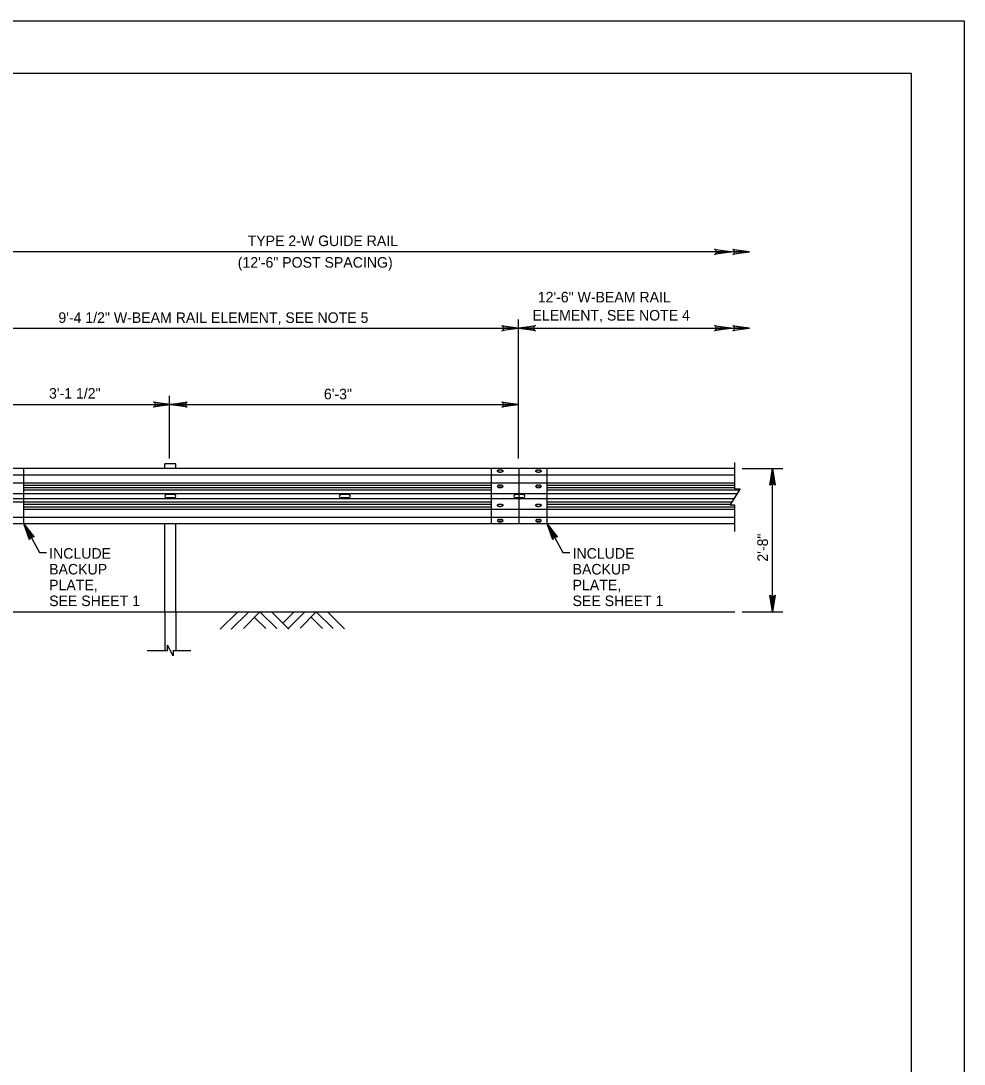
# Model space of a CAD drawing. Extents: x 637628 to 640188, y 298266 to 300751.
# Drawn here: x 639692 to 639960.5, y 299156.6 to 299453.6 of the extents above; entities that cross this region are included whole.
import ezdxf

# ---------------------------------------------------------------- set-up
doc = ezdxf.new("R2010")
doc.units = 0
for name, color, linetype in [('1', 7, 'Continuous'), ('2', 7, 'Continuous'), ('PLT-BNDY', 7, 'Continuous'), ('S-ABUT-CONC', 7, 'Continuous'), ('S-ANNO-CELL', 7, 'Continuous')]:
    doc.layers.add(name, color=color, linetype=linetype)

msp = doc.modelspace()

# ---------------------------------------------------------------- linework, layer by layer
at = {"layer": '1'}
for p, q in [((639692.9, 299310.39), (639692.9, 299326.12)), ((639825.97, 299310.39), (639825.97, 299326.12)), ((639841.88, 299310.39), (639841.88, 299326.12))]:
    msp.add_line(p, q, dxfattribs=at)
msp.add_lwpolyline([(639945.52, 298874.58), (639945.52, 299438.55), (639159.55, 299438.55), (639159.55, 298874.58), (639945.52, 298874.58), (639945.52, 298900.93), (639745.53, 298900.93), (639745.53, 298965.61), (639945.52, 298965.61), (639945.52, 298994.57), (639745.53, 298994.57), (639745.53, 298874.58), (639824.33, 298874.58), (639824.33, 298900.93), (639824.33, 298874.58), (639901.33, 298874.58), (639901.33, 298900.93), (639901.33, 298888.62), (639945.52, 298888.62)], dxfattribs=at)
at = {"layer": '2'}
for p, q in [((639753.59, 299285.19), (639748.82, 299280.42)), ((639756.7, 299285.19), (639751.92, 299280.42)), ((639760.11, 299285.32), (639755.38, 299280.59)), ((639764.88, 299280.55), (639760.11, 299285.32)), ((639768.29, 299280.42), (639763.56, 299285.15)), ((639769.71, 299285.29), (639766.57, 299282.14)), ((639772.82, 299285.29), (639768.05, 299280.52)), ((639776.13, 299285.32), (639771.5, 299280.69)), ((639780.91, 299280.55), (639776.13, 299285.32)), ((639784.15, 299280.52), (639779.35, 299285.32)), ((639761.77, 299280.55), (639758.55, 299283.77)), ((639777.9, 299280.56), (639774.68, 299283.78))]:
    msp.add_line(p, q, dxfattribs=at)
for points in [[(639889.73, 299388.36), (639889.89, 299388.03), (639894.26, 299387.79), (639889.73, 299388.36), (639889.49, 299388.56), (639894.26, 299387.79), (639889.9, 299387.58), (639889.74, 299387.25), (639894.26, 299387.79), (639889.49, 299387.03), (639889.74, 299387.25)], [(639894.92, 299388.38), (639895.09, 299388.06), (639899.46, 299387.82), (639894.92, 299388.38), (639894.69, 299388.58), (639899.46, 299387.82), (639895.09, 299387.6), (639894.93, 299387.27), (639899.46, 299387.82), (639894.69, 299387.06), (639894.93, 299387.27)], [(639829.17, 299366.65), (639829.34, 299366.32), (639833.71, 299366.09), (639829.17, 299366.65), (639828.94, 299366.85), (639833.71, 299366.09), (639829.35, 299365.87), (639829.18, 299365.54), (639833.71, 299366.09), (639828.94, 299365.32), (639829.18, 299365.54)], [(639838.25, 299365.52), (639838.08, 299365.85), (639833.71, 299366.09), (639838.25, 299365.52), (639838.48, 299365.32), (639833.71, 299366.09), (639838.08, 299366.3), (639838.24, 299366.63), (639833.71, 299366.09), (639838.48, 299366.85), (639838.24, 299366.63)], [(639889.73, 299366.63), (639889.89, 299366.3), (639894.26, 299366.06), (639889.73, 299366.63), (639889.49, 299366.83), (639894.26, 299366.06), (639889.9, 299365.85), (639889.74, 299365.52), (639894.26, 299366.06), (639889.49, 299365.3), (639889.74, 299365.52)], [(639894.92, 299366.65), (639895.09, 299366.32), (639899.46, 299366.09), (639894.92, 299366.65), (639894.69, 299366.85), (639899.46, 299366.09), (639895.09, 299365.87), (639894.93, 299365.54), (639899.46, 299366.09), (639894.69, 299365.32), (639894.93, 299365.54)], [(639730.06, 299344.9), (639730.23, 299344.57), (639734.6, 299344.33), (639730.06, 299344.9), (639729.83, 299345.1), (639734.6, 299344.33), (639730.24, 299344.12), (639730.08, 299343.79), (639734.6, 299344.33), (639729.83, 299343.57), (639730.08, 299343.79)], [(639739.14, 299343.76), (639738.97, 299344.09), (639734.6, 299344.33), (639739.14, 299343.76), (639739.38, 299343.56), (639734.6, 299344.33), (639738.97, 299344.55), (639739.13, 299344.87), (639734.6, 299344.33), (639739.38, 299345.09), (639739.13, 299344.87)], [(639829.17, 299344.9), (639829.34, 299344.57), (639833.71, 299344.33), (639829.17, 299344.9), (639828.94, 299345.1), (639833.71, 299344.33), (639829.35, 299344.12), (639829.18, 299343.79), (639833.71, 299344.33), (639828.94, 299343.57), (639829.18, 299343.79)], [(639905.41, 299321.63), (639905.74, 299321.79), (639905.98, 299326.17), (639905.41, 299321.63), (639905.21, 299321.39), (639905.98, 299326.17), (639906.19, 299321.8), (639906.52, 299321.64), (639905.98, 299326.17), (639906.74, 299321.39), (639906.52, 299321.64)], [(639694.57, 299306.13), (639694.77, 299306.43), (639692.9, 299310.39), (639694.57, 299306.13), (639694.5, 299305.83), (639692.9, 299310.39), (639695.17, 299306.65), (639695.54, 299306.67), (639692.9, 299310.39), (639695.84, 299306.56), (639695.54, 299306.67)], [(639843.55, 299306.13), (639843.75, 299306.43), (639841.88, 299310.39), (639843.55, 299306.13), (639843.48, 299305.83), (639841.88, 299310.39), (639844.15, 299306.65), (639844.52, 299306.67), (639841.88, 299310.39), (639844.82, 299306.56), (639844.52, 299306.67)], [(639906.54, 299289.87), (639906.21, 299289.7), (639905.98, 299285.33), (639906.54, 299289.87), (639906.74, 299290.1), (639905.98, 299285.33), (639905.76, 299289.69), (639905.43, 299289.85), (639905.98, 299285.33), (639905.21, 299290.1), (639905.43, 299289.85)]]:
    msp.add_lwpolyline(points, dxfattribs=at)
at = {"layer": 'PLT-BNDY'}
msp.add_lwpolyline([(639119.52, 299453.58), (639960.52, 299453.58), (639960.52, 298859.58), (639119.52, 298859.58)], close=True, dxfattribs=at)
at = {"layer": 'S-ABUT-CONC'}
for p, q in [((639899.46, 299387.84), (639684.94, 299387.84)), ((639833.71, 299328.97), (639833.71, 299368.55)), ((639684.94, 299366.09), (639833.71, 299366.09)), ((639833.71, 299366.09), (639899.46, 299366.09)), ((639734.39, 299328.97), (639734.39, 299346.82)), ((639684.94, 299344.33), (639734.6, 299344.33)), ((639734.6, 299344.33), (639833.71, 299344.33)), ((639897.33, 299326.17), (639908.91, 299326.17)), ((639905.98, 299285.33), (639905.98, 299326.17)), ((639692.9, 299310.39), (639697.31, 299302.27)), ((639841.88, 299310.39), (639846.29, 299302.27)), ((639697.31, 299302.27), (639699.3, 299302.27)), ((639846.29, 299302.27), (639848.28, 299302.27)), ((639897.33, 299285.33), (639908.91, 299285.33))]:
    msp.add_line(p, q, dxfattribs=at)
at = {"layer": 'S-ANNO-CELL'}
for p, q in [((639895.3, 299326.12), (639676.99, 299326.12)), ((639736.19, 299327.51), (639733.01, 299327.51)), ((639733.01, 299326.12), (639733.01, 299327.51)), ((639736.19, 299326.12), (639736.19, 299327.51)), ((639828.31, 299325.77), (639828.63, 299325.77)), ((639828.31, 299325.66), (639828.31, 299325.77)), ((639828.63, 299325.66), (639828.31, 299325.66)), ((639828.63, 299325.66), (639828.63, 299325.77)), ((639833.92, 299310.52), (639833.92, 299326.12)), ((639839.22, 299325.77), (639839.54, 299325.77)), ((639839.22, 299325.66), (639839.22, 299325.77)), ((639839.54, 299325.66), (639839.22, 299325.66)), ((639839.54, 299325.66), (639839.54, 299325.77)), ((639895.3, 299320.31), (639895.3, 299327.81)), ((639825.97, 299324.27), (639676.99, 299324.27)), ((639895.3, 299324.27), (639825.97, 299324.27)), ((639828.31, 299325.06), (639828.63, 299325.06)), ((639839.22, 299325.06), (639839.54, 299325.06)), ((639825.97, 299322.01), (639676.99, 299322.01)), ((639825.97, 299321.32), (639692.9, 299321.32)), ((639825.97, 299320.63), (639692.9, 299320.63)), ((639825.97, 299319.95), (639692.9, 299319.95)), ((639895.3, 299322.01), (639825.97, 299322.01)), ((639828.31, 299321.42), (639828.63, 299321.42)), ((639828.31, 299320.82), (639828.31, 299320.71)), ((639828.63, 299320.82), (639828.31, 299320.82)), ((639828.31, 299320.71), (639828.63, 299320.71)), ((639828.63, 299320.82), (639828.63, 299320.71)), ((639839.22, 299321.42), (639839.54, 299321.42)), ((639839.22, 299320.82), (639839.22, 299320.71)), ((639839.54, 299320.82), (639839.22, 299320.82)), ((639839.22, 299320.71), (639839.54, 299320.71)), ((639839.54, 299320.82), (639839.54, 299320.71)), ((639895.3, 299321.32), (639841.88, 299321.32)), ((639895.3, 299320.63), (639841.88, 299320.63)), ((639896.57, 299319.95), (639841.88, 299319.95)), ((639896.8, 299320.31), (639893.8, 299315.67)), ((639895.3, 299320.31), (639896.8, 299320.31)), ((639825.97, 299318.95), (639676.99, 299318.95)), ((639825.97, 299317.55), (639676.99, 299317.55)), ((639734.6, 299318.73), (639733.49, 299318.73)), ((639734.6, 299317.77), (639733.49, 299317.77)), ((639735.72, 299318.73), (639734.6, 299318.73)), ((639735.72, 299317.77), (639734.6, 299317.77)), ((639784.26, 299318.73), (639783.15, 299318.73)), ((639784.26, 299317.77), (639783.15, 299317.77)), ((639785.38, 299318.73), (639784.26, 299318.73)), ((639785.38, 299317.77), (639784.26, 299317.77)), ((639895.92, 299318.95), (639825.97, 299318.95)), ((639895.02, 299317.55), (639825.97, 299317.55)), ((639833.92, 299318.73), (639832.81, 299318.73)), ((639833.92, 299317.77), (639832.81, 299317.77)), ((639835.04, 299318.73), (639833.92, 299318.73)), ((639835.04, 299317.77), (639833.92, 299317.77)), ((639825.97, 299316.56), (639676.99, 299316.56)), ((639825.97, 299315.87), (639692.9, 299315.87)), ((639825.97, 299315.14), (639692.9, 299315.14)), ((639825.97, 299314.45), (639692.9, 299314.45)), ((639895.3, 299314.45), (639825.97, 299314.45)), ((639828.31, 299316.02), (639828.63, 299316.02)), ((639828.31, 299315.91), (639828.31, 299316.02)), ((639828.63, 299315.91), (639828.31, 299315.91)), ((639828.31, 299315.31), (639828.63, 299315.31)), ((639828.63, 299315.91), (639828.63, 299316.02)), ((639839.22, 299316.02), (639839.54, 299316.02)), ((639839.22, 299315.91), (639839.22, 299316.02)), ((639839.54, 299315.91), (639839.22, 299315.91)), ((639839.22, 299315.31), (639839.54, 299315.31)), ((639839.54, 299315.91), (639839.54, 299316.02)), ((639894.38, 299316.56), (639841.88, 299316.56)), ((639893.93, 299315.87), (639841.88, 299315.87)), ((639895.3, 299315.14), (639841.88, 299315.14)), ((639895.3, 299315.67), (639893.8, 299315.67)), ((639895.3, 299308.17), (639895.3, 299315.67)), ((639825.97, 299312.24), (639676.99, 299312.24)), ((639895.3, 299312.24), (639825.97, 299312.24)), ((639828.31, 299311.67), (639828.63, 299311.67)), ((639828.31, 299311.07), (639828.31, 299310.96)), ((639828.63, 299311.07), (639828.31, 299311.07)), ((639828.31, 299310.96), (639828.63, 299310.96)), ((639828.63, 299311.07), (639828.63, 299310.96)), ((639839.22, 299311.67), (639839.54, 299311.67)), ((639839.22, 299311.07), (639839.22, 299310.96)), ((639839.54, 299311.07), (639839.22, 299311.07)), ((639839.22, 299310.96), (639839.54, 299310.96)), ((639839.54, 299311.07), (639839.54, 299310.96)), ((639825.97, 299310.39), (639676.99, 299310.39)), ((639733.01, 299285.33), (639733.01, 299310.39)), ((639736.19, 299285.33), (639736.19, 299310.39)), ((639895.3, 299310.39), (639825.97, 299310.39)), ((639581.11, 299285.33), (639895.3, 299285.33)), ((639733.01, 299285.33), (639733.01, 299274.31)), ((639736.19, 299285.33), (639736.19, 299274.31)), ((639733.78, 299274.31), (639733.78, 299275.81)), ((639735.42, 299272.81), (639733.78, 299275.81)), ((639728.01, 299274.31), (639732.24, 299274.31)), ((639728.78, 299274.31), (639733.78, 299274.31)), ((639735.42, 299274.31), (639735.42, 299272.81)), ((639735.42, 299274.31), (639740.42, 299274.31))]:
    msp.add_line(p, q, dxfattribs=at)
for points in [[(639828.31, 299325.06), (639828.2, 299325.07), (639828.09, 299325.08), (639827.99, 299325.11), (639827.9, 299325.15), (639827.82, 299325.19), (639827.76, 299325.24), (639827.71, 299325.3), (639827.68, 299325.36), (639827.67, 299325.42), (639827.68, 299325.48), (639827.71, 299325.54), (639827.76, 299325.6), (639827.82, 299325.65), (639827.9, 299325.69), (639827.99, 299325.73), (639828.09, 299325.75), (639828.2, 299325.77), (639828.31, 299325.77)], [(639828.31, 299325.66), (639828.2, 299325.66), (639828.09, 299325.64), (639827.99, 299325.62), (639827.9, 299325.58), (639827.82, 299325.54), (639827.76, 299325.49), (639827.71, 299325.43), (639827.68, 299325.37), (639827.68, 299325.36)], [(639828.63, 299325.77), (639828.74, 299325.77), (639828.84, 299325.75), (639828.94, 299325.73), (639829.03, 299325.69), (639829.11, 299325.65), (639829.18, 299325.6), (639829.22, 299325.54), (639829.25, 299325.48), (639829.26, 299325.42), (639829.25, 299325.36), (639829.22, 299325.3), (639829.18, 299325.24), (639829.11, 299325.19), (639829.03, 299325.15), (639828.94, 299325.11), (639828.84, 299325.08), (639828.74, 299325.07), (639828.63, 299325.06)], [(639829.25, 299325.36), (639829.25, 299325.37), (639829.22, 299325.43), (639829.18, 299325.49), (639829.11, 299325.54), (639829.03, 299325.58), (639828.94, 299325.62), (639828.84, 299325.64), (639828.74, 299325.66), (639828.63, 299325.66)], [(639839.22, 299325.06), (639839.11, 299325.07), (639839, 299325.08), (639838.9, 299325.11), (639838.81, 299325.15), (639838.73, 299325.19), (639838.67, 299325.24), (639838.62, 299325.3), (639838.59, 299325.36), (639838.58, 299325.42), (639838.59, 299325.48), (639838.62, 299325.54), (639838.67, 299325.6), (639838.73, 299325.65), (639838.81, 299325.69), (639838.9, 299325.73), (639839, 299325.75), (639839.11, 299325.77), (639839.22, 299325.77)], [(639839.22, 299325.66), (639839.11, 299325.66), (639839, 299325.64), (639838.9, 299325.62), (639838.81, 299325.58), (639838.73, 299325.54), (639838.67, 299325.49), (639838.62, 299325.43), (639838.59, 299325.37), (639838.59, 299325.36)], [(639839.54, 299325.77), (639839.65, 299325.77), (639839.76, 299325.75), (639839.86, 299325.73), (639839.95, 299325.69), (639840.03, 299325.65), (639840.09, 299325.6), (639840.14, 299325.54), (639840.17, 299325.48), (639840.18, 299325.42), (639840.17, 299325.36), (639840.14, 299325.3), (639840.09, 299325.24), (639840.03, 299325.19), (639839.95, 299325.15), (639839.86, 299325.11), (639839.76, 299325.08), (639839.65, 299325.07), (639839.54, 299325.06)], [(639840.17, 299325.36), (639840.17, 299325.37), (639840.14, 299325.43), (639840.09, 299325.49), (639840.03, 299325.54), (639839.95, 299325.58), (639839.86, 299325.62), (639839.76, 299325.64), (639839.65, 299325.66), (639839.54, 299325.66)], [(639828.31, 299321.42), (639828.2, 299321.42), (639828.09, 299321.4), (639827.99, 299321.37), (639827.9, 299321.34), (639827.82, 299321.29), (639827.76, 299321.24), (639827.71, 299321.19), (639827.68, 299321.13), (639827.67, 299321.06), (639827.68, 299321), (639827.71, 299320.94), (639827.76, 299320.89), (639827.82, 299320.84), (639827.9, 299320.79), (639827.99, 299320.76), (639828.09, 299320.73), (639828.2, 299320.71), (639828.31, 299320.71)], [(639828.31, 299320.82), (639828.2, 299320.82), (639828.09, 299320.84), (639827.99, 299320.87), (639827.9, 299320.9), (639827.82, 299320.95), (639827.76, 299321), (639827.71, 299321.05), (639827.68, 299321.11), (639827.68, 299321.12)], [(639828.63, 299320.71), (639828.74, 299320.71), (639828.84, 299320.73), (639828.94, 299320.76), (639829.03, 299320.79), (639829.11, 299320.84), (639829.18, 299320.89), (639829.22, 299320.94), (639829.25, 299321), (639829.26, 299321.06), (639829.25, 299321.13), (639829.22, 299321.19), (639829.18, 299321.24), (639829.11, 299321.29), (639829.03, 299321.34), (639828.94, 299321.37), (639828.84, 299321.4), (639828.74, 299321.42), (639828.63, 299321.42)], [(639829.25, 299321.12), (639829.25, 299321.11), (639829.22, 299321.05), (639829.18, 299321), (639829.11, 299320.95), (639829.03, 299320.9), (639828.94, 299320.87), (639828.84, 299320.84), (639828.74, 299320.82), (639828.63, 299320.82)], [(639839.22, 299321.42), (639839.11, 299321.42), (639839, 299321.4), (639838.9, 299321.37), (639838.81, 299321.34), (639838.73, 299321.29), (639838.67, 299321.24), (639838.62, 299321.19), (639838.59, 299321.13), (639838.58, 299321.06), (639838.59, 299321), (639838.62, 299320.94), (639838.67, 299320.89), (639838.73, 299320.84), (639838.81, 299320.79), (639838.9, 299320.76), (639839, 299320.73), (639839.11, 299320.71), (639839.22, 299320.71)], [(639839.22, 299320.82), (639839.11, 299320.82), (639839, 299320.84), (639838.9, 299320.87), (639838.81, 299320.9), (639838.73, 299320.95), (639838.67, 299321), (639838.62, 299321.05), (639838.59, 299321.11), (639838.59, 299321.12)], [(639839.54, 299320.71), (639839.65, 299320.71), (639839.76, 299320.73), (639839.86, 299320.76), (639839.95, 299320.79), (639840.03, 299320.84), (639840.09, 299320.89), (639840.14, 299320.94), (639840.17, 299321), (639840.18, 299321.06), (639840.17, 299321.13), (639840.14, 299321.19), (639840.09, 299321.24), (639840.03, 299321.29), (639839.95, 299321.34), (639839.86, 299321.37), (639839.76, 299321.4), (639839.65, 299321.42), (639839.54, 299321.42)], [(639840.17, 299321.12), (639840.17, 299321.11), (639840.14, 299321.05), (639840.09, 299321), (639840.03, 299320.95), (639839.95, 299320.9), (639839.86, 299320.87), (639839.76, 299320.84), (639839.65, 299320.82), (639839.54, 299320.82)], [(639828.31, 299315.31), (639828.2, 299315.32), (639828.09, 299315.33), (639827.99, 299315.36), (639827.9, 299315.4), (639827.82, 299315.44), (639827.76, 299315.49), (639827.71, 299315.55), (639827.68, 299315.61), (639827.67, 299315.67), (639827.68, 299315.73), (639827.71, 299315.79), (639827.76, 299315.85), (639827.82, 299315.9), (639827.9, 299315.94), (639827.99, 299315.98), (639828.09, 299316), (639828.2, 299316.02), (639828.31, 299316.02)], [(639828.31, 299315.91), (639828.2, 299315.91), (639828.09, 299315.89), (639827.99, 299315.87), (639827.9, 299315.83), (639827.82, 299315.79), (639827.76, 299315.74), (639827.71, 299315.68), (639827.68, 299315.62), (639827.68, 299315.61)], [(639828.63, 299316.02), (639828.74, 299316.02), (639828.84, 299316), (639828.94, 299315.98), (639829.03, 299315.94), (639829.11, 299315.9), (639829.18, 299315.85), (639829.22, 299315.79), (639829.25, 299315.73), (639829.26, 299315.67), (639829.25, 299315.61), (639829.22, 299315.55), (639829.18, 299315.49), (639829.11, 299315.44), (639829.03, 299315.4), (639828.94, 299315.36), (639828.84, 299315.33), (639828.74, 299315.32), (639828.63, 299315.31)], [(639829.25, 299315.61), (639829.25, 299315.62), (639829.22, 299315.68), (639829.18, 299315.74), (639829.11, 299315.79), (639829.03, 299315.83), (639828.94, 299315.87), (639828.84, 299315.89), (639828.74, 299315.91), (639828.63, 299315.91)], [(639839.22, 299315.31), (639839.11, 299315.32), (639839, 299315.33), (639838.9, 299315.36), (639838.81, 299315.4), (639838.73, 299315.44), (639838.67, 299315.49), (639838.62, 299315.55), (639838.59, 299315.61), (639838.58, 299315.67), (639838.59, 299315.73), (639838.62, 299315.79), (639838.67, 299315.85), (639838.73, 299315.9), (639838.81, 299315.94), (639838.9, 299315.98), (639839, 299316), (639839.11, 299316.02), (639839.22, 299316.02)], [(639839.22, 299315.91), (639839.11, 299315.91), (639839, 299315.89), (639838.9, 299315.87), (639838.81, 299315.83), (639838.73, 299315.79), (639838.67, 299315.74), (639838.62, 299315.68), (639838.59, 299315.62), (639838.59, 299315.61)], [(639839.54, 299316.02), (639839.65, 299316.02), (639839.76, 299316), (639839.86, 299315.98), (639839.95, 299315.94), (639840.03, 299315.9), (639840.09, 299315.85), (639840.14, 299315.79), (639840.17, 299315.73), (639840.18, 299315.67), (639840.17, 299315.61), (639840.14, 299315.55), (639840.09, 299315.49), (639840.03, 299315.44), (639839.95, 299315.4), (639839.86, 299315.36), (639839.76, 299315.33), (639839.65, 299315.32), (639839.54, 299315.31)], [(639840.17, 299315.61), (639840.17, 299315.62), (639840.14, 299315.68), (639840.09, 299315.74), (639840.03, 299315.79), (639839.95, 299315.83), (639839.86, 299315.87), (639839.76, 299315.89), (639839.65, 299315.91), (639839.54, 299315.91)], [(639828.31, 299311.67), (639828.2, 299311.67), (639828.09, 299311.65), (639827.99, 299311.62), (639827.9, 299311.59), (639827.82, 299311.54), (639827.76, 299311.49), (639827.71, 299311.44), (639827.68, 299311.38), (639827.67, 299311.31), (639827.68, 299311.25), (639827.71, 299311.19), (639827.76, 299311.14), (639827.82, 299311.09), (639827.9, 299311.04), (639827.99, 299311.01), (639828.09, 299310.98), (639828.2, 299310.96), (639828.31, 299310.96)], [(639828.31, 299311.07), (639828.2, 299311.07), (639828.09, 299311.09), (639827.99, 299311.12), (639827.9, 299311.15), (639827.82, 299311.2), (639827.76, 299311.25), (639827.71, 299311.3), (639827.68, 299311.36), (639827.68, 299311.37)], [(639828.63, 299310.96), (639828.74, 299310.96), (639828.84, 299310.98), (639828.94, 299311.01), (639829.03, 299311.04), (639829.11, 299311.09), (639829.18, 299311.14), (639829.22, 299311.19), (639829.25, 299311.25), (639829.26, 299311.31), (639829.25, 299311.38), (639829.22, 299311.44), (639829.18, 299311.49), (639829.11, 299311.54), (639829.03, 299311.59), (639828.94, 299311.62), (639828.84, 299311.65), (639828.74, 299311.67), (639828.63, 299311.67)], [(639829.25, 299311.37), (639829.25, 299311.36), (639829.22, 299311.3), (639829.18, 299311.25), (639829.11, 299311.2), (639829.03, 299311.15), (639828.94, 299311.12), (639828.84, 299311.09), (639828.74, 299311.07), (639828.63, 299311.07)], [(639839.22, 299311.67), (639839.11, 299311.67), (639839, 299311.65), (639838.9, 299311.62), (639838.81, 299311.59), (639838.73, 299311.54), (639838.67, 299311.49), (639838.62, 299311.44), (639838.59, 299311.38), (639838.58, 299311.31), (639838.59, 299311.25), (639838.62, 299311.19), (639838.67, 299311.14), (639838.73, 299311.09), (639838.81, 299311.04), (639838.9, 299311.01), (639839, 299310.98), (639839.11, 299310.96), (639839.22, 299310.96)], [(639839.22, 299311.07), (639839.11, 299311.07), (639839, 299311.09), (639838.9, 299311.12), (639838.81, 299311.15), (639838.73, 299311.2), (639838.67, 299311.25), (639838.62, 299311.3), (639838.59, 299311.36), (639838.59, 299311.37)], [(639839.54, 299310.96), (639839.65, 299310.96), (639839.76, 299310.98), (639839.86, 299311.01), (639839.95, 299311.04), (639840.03, 299311.09), (639840.09, 299311.14), (639840.14, 299311.19), (639840.17, 299311.25), (639840.18, 299311.31), (639840.17, 299311.38), (639840.14, 299311.44), (639840.09, 299311.49), (639840.03, 299311.54), (639839.95, 299311.59), (639839.86, 299311.62), (639839.76, 299311.65), (639839.65, 299311.67), (639839.54, 299311.67)], [(639840.17, 299311.37), (639840.17, 299311.36), (639840.14, 299311.3), (639840.09, 299311.25), (639840.03, 299311.2), (639839.95, 299311.15), (639839.86, 299311.12), (639839.76, 299311.09), (639839.65, 299311.07), (639839.54, 299311.07)]]:
    msp.add_lwpolyline(points, dxfattribs=at)
for centre, start, end in [((639733.49, 299318.25), 90, 270), ((639735.72, 299318.25), 270, 90), ((639783.15, 299318.25), 90, 270), ((639785.38, 299318.25), 270, 90), ((639832.81, 299318.25), 90, 270), ((639835.04, 299318.25), 270, 90)]:
    msp.add_arc(centre, 0.478, start, end, dxfattribs=at)

# ---------------------------------------------------------------- texts
at = {"layer": 'S-ABUT-CONC'}
for s, p in [('TYPE 2-W GUIDE RAIL', (639756.59, 299389.46)), ('(12\'-6" POST SPACING)', (639753.77, 299383.32)), ('12\'-6" W-BEAM RAIL ', (639839.17, 299373.43)), ('9\'-4 1/2" W-BEAM RAIL ELEMENT, SEE NOTE 5', (639702.72, 299367.59)), ('ELEMENT, SEE NOTE 4', (639837.67, 299368.27)), ('3\'-1 1/2"', (639700.06, 299346.04)), ('6\'-3"', (639778.3, 299345.83)), ('INCLUDE ', (639700.1, 299300.47)), ('INCLUDE', (639849.08, 299300.47)), ('BACKUP', (639700.1, 299295.97)), ('BACKUP', (639849.08, 299295.97)), ('PLATE, ', (639700.1, 299291.47)), ('PLATE, ', (639849.08, 299291.47)), ('SEE SHEET 1', (639700.1, 299286.97)), ('SEE SHEET 1', (639849.08, 299286.97))]:
    msp.add_text(s, height=3, dxfattribs=at).set_placement(p)
msp.add_text('2\'-8"', height=3, rotation=90, dxfattribs=at).set_placement((639904.67, 299299.63))

doc.saveas('drawing.dxf')
